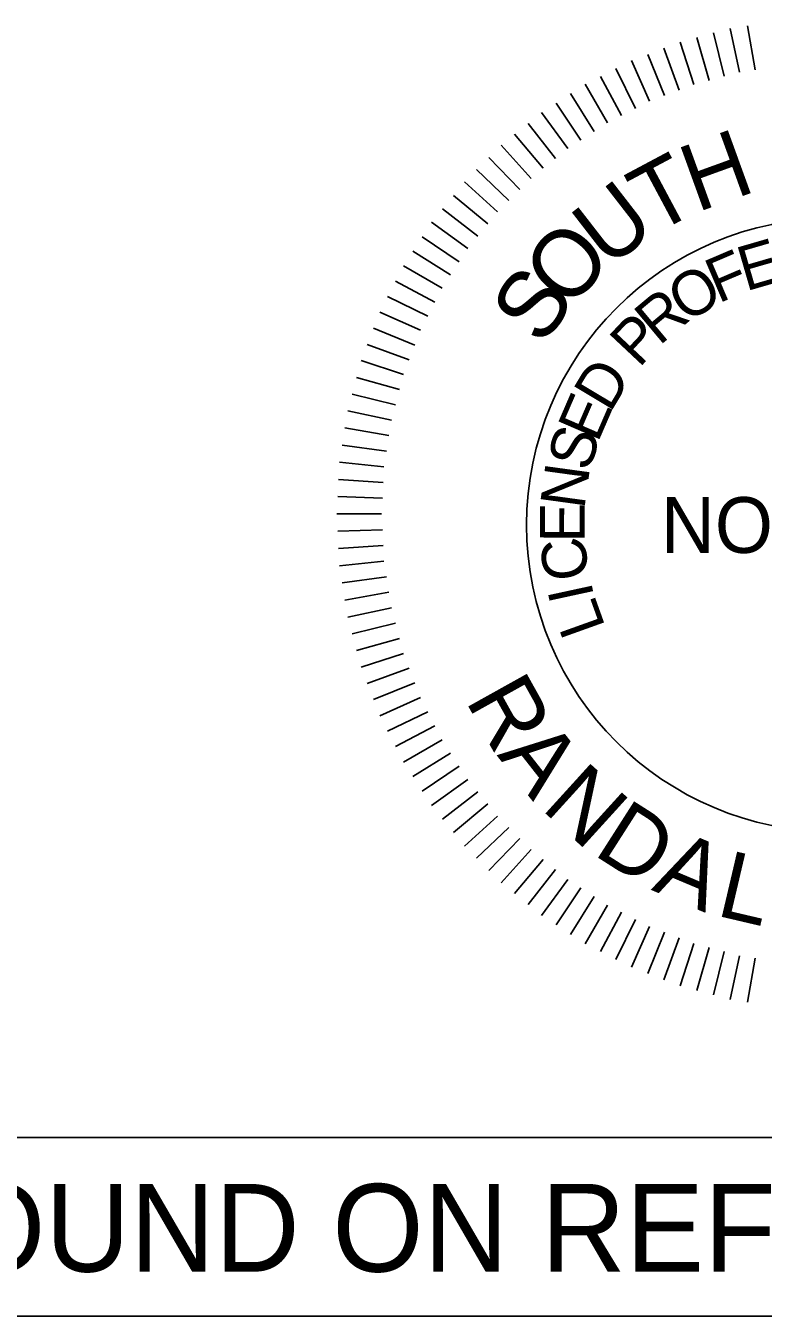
# Model space of a CAD drawing. Extents: x 1964849 to 1967422, y 1116563 to 1122211.
# Drawn here: x 1967263.8 to 1967322.6, y 1120529.2 to 1120632.2 of the extents above; entities that cross this region are included whole.
import ezdxf

# ---------------------------------------------------------------- set-up
doc = ezdxf.new("R2010")
doc.units = 0
doc.layers.add('RD_Sketch1', color=7, linetype='Continuous')
doc.layers.add('RD_TX_PEShield', color=7, linetype='Continuous')

msp = doc.modelspace()

# ---------------------------------------------------------------- linework, layer by layer
at = {"layer": 'RD_Sketch1'}
msp.add_lwpolyline([(1967105.7, 1120543.48), (1967406.12, 1120543.48), (1967406.12, 1120529.22), (1967105.7, 1120529.22)], close=True, dxfattribs=at)
at = {"layer": 'RD_TX_PEShield'}
for p, q in [((1967319.52, 1120628.17), (1967318.66, 1120631.62)), ((1967319.52, 1120628.17), (1967318.66, 1120631.62)), ((1967320.73, 1120628.5), (1967319.99, 1120631.98)), ((1967320.73, 1120628.5), (1967319.99, 1120631.98)), ((1967321.97, 1120628.69), (1967321.36, 1120632.19)), ((1967321.97, 1120628.69), (1967321.36, 1120632.19)), ((1967315.91, 1120627.07), (1967314.7, 1120630.41)), ((1967315.91, 1120627.07), (1967314.7, 1120630.41)), ((1967317.09, 1120627.52), (1967315.99, 1120630.9)), ((1967317.09, 1120627.52), (1967315.99, 1120630.9)), ((1967318.3, 1120627.84), (1967317.32, 1120631.26)), ((1967318.3, 1120627.84), (1967317.32, 1120631.26)), ((1967313.56, 1120626.17), (1967312.12, 1120629.42)), ((1967313.56, 1120626.17), (1967312.12, 1120629.42)), ((1967314.74, 1120626.62), (1967313.41, 1120629.91)), ((1967314.74, 1120626.62), (1967313.41, 1120629.91)), ((1967312.44, 1120625.6), (1967310.88, 1120628.79)), ((1967312.44, 1120625.6), (1967310.88, 1120628.79)), ((1967310.2, 1120624.45), (1967308.42, 1120627.54)), ((1967310.2, 1120624.45), (1967308.42, 1120627.54)), ((1967311.32, 1120625.03), (1967309.65, 1120628.16)), ((1967311.32, 1120625.03), (1967309.65, 1120628.16)), ((1967309.15, 1120623.77), (1967307.26, 1120626.78)), ((1967309.15, 1120623.77), (1967307.26, 1120626.78)), ((1967307.04, 1120622.4), (1967304.95, 1120625.28)), ((1967307.04, 1120622.4), (1967304.95, 1120625.28)), ((1967308.09, 1120623.08), (1967306.11, 1120626.03)), ((1967308.09, 1120623.08), (1967306.11, 1120626.03)), ((1967306.06, 1120621.61), (1967303.87, 1120624.41)), ((1967306.06, 1120621.61), (1967303.87, 1120624.41)), ((1967305.08, 1120620.82), (1967302.8, 1120623.54)), ((1967305.08, 1120620.82), (1967302.8, 1120623.54)), ((1967304.11, 1120620.02), (1967301.72, 1120622.67)), ((1967304.11, 1120620.02), (1967301.72, 1120622.67)), ((1967303.22, 1120619.14), (1967300.75, 1120621.69)), ((1967303.22, 1120619.14), (1967300.75, 1120621.69)), ((1967302.33, 1120618.25), (1967299.77, 1120620.72)), ((1967302.33, 1120618.25), (1967299.77, 1120620.72)), ((1967301.44, 1120617.36), (1967298.79, 1120619.74)), ((1967301.44, 1120617.36), (1967298.79, 1120619.74)), ((1967300.65, 1120616.38), (1967297.92, 1120618.66)), ((1967300.65, 1120616.38), (1967297.92, 1120618.66)), ((1967299.86, 1120615.4), (1967297.05, 1120617.59)), ((1967299.86, 1120615.4), (1967297.05, 1120617.59)), ((1967299.06, 1120614.42), (1967296.18, 1120616.52)), ((1967299.06, 1120614.42), (1967296.18, 1120616.52)), ((1967298.38, 1120613.37), (1967295.43, 1120615.36)), ((1967298.38, 1120613.37), (1967295.43, 1120615.36)), ((1967297.69, 1120612.32), (1967294.68, 1120614.2)), ((1967297.69, 1120612.32), (1967294.68, 1120614.2)), ((1967297.01, 1120611.26), (1967293.93, 1120613.04)), ((1967297.01, 1120611.26), (1967293.93, 1120613.04)), ((1967296.44, 1120610.14), (1967293.3, 1120611.81)), ((1967296.44, 1120610.14), (1967293.3, 1120611.81)), ((1967295.87, 1120609.02), (1967292.67, 1120610.58)), ((1967295.87, 1120609.02), (1967292.67, 1120610.58)), ((1967295.3, 1120607.9), (1967292.04, 1120609.35)), ((1967295.3, 1120607.9), (1967292.04, 1120609.35)), ((1967294.85, 1120606.72), (1967291.55, 1120608.06)), ((1967294.85, 1120606.72), (1967291.55, 1120608.06)), ((1967294.4, 1120605.55), (1967291.05, 1120606.77)), ((1967294.4, 1120605.55), (1967291.05, 1120606.77)), ((1967293.94, 1120604.38), (1967290.56, 1120605.48)), ((1967293.94, 1120604.38), (1967290.56, 1120605.48)), ((1967293.62, 1120603.16), (1967290.2, 1120604.14)), ((1967293.62, 1120603.16), (1967290.2, 1120604.14)), ((1967293.29, 1120601.95), (1967289.84, 1120602.81)), ((1967293.29, 1120601.95), (1967289.84, 1120602.81)), ((1967292.97, 1120600.73), (1967289.49, 1120601.47)), ((1967292.97, 1120600.73), (1967289.49, 1120601.47)), ((1967292.77, 1120599.49), (1967289.27, 1120600.11)), ((1967292.77, 1120599.49), (1967289.27, 1120600.11)), ((1967292.57, 1120598.25), (1967289.05, 1120598.74)), ((1967292.57, 1120598.25), (1967289.05, 1120598.74)), ((1967292.38, 1120597.01), (1967288.84, 1120597.38)), ((1967292.38, 1120597.01), (1967288.84, 1120597.38)), ((1967292.31, 1120595.75), (1967288.76, 1120596)), ((1967292.31, 1120595.75), (1967288.76, 1120596)), ((1967292.25, 1120594.49), (1967288.69, 1120594.62)), ((1967292.25, 1120594.49), (1967288.69, 1120594.62)), ((1967292.18, 1120593.24), (1967288.62, 1120593.24)), ((1967292.18, 1120593.24), (1967288.62, 1120593.24)), ((1967292.25, 1120591.98), (1967288.69, 1120591.86)), ((1967292.25, 1120591.98), (1967288.69, 1120591.86)), ((1967292.31, 1120590.73), (1967288.76, 1120590.48)), ((1967292.31, 1120590.73), (1967288.76, 1120590.48)), ((1967292.38, 1120589.47), (1967288.84, 1120589.1)), ((1967292.38, 1120589.47), (1967288.84, 1120589.1)), ((1967292.57, 1120588.23), (1967289.05, 1120587.73)), ((1967292.57, 1120588.23), (1967289.05, 1120587.73)), ((1967292.77, 1120586.99), (1967289.27, 1120586.37)), ((1967292.77, 1120586.99), (1967289.27, 1120586.37)), ((1967292.97, 1120585.74), (1967289.49, 1120585)), ((1967292.97, 1120585.74), (1967289.49, 1120585)), ((1967293.29, 1120584.53), (1967289.84, 1120583.67)), ((1967293.29, 1120584.53), (1967289.84, 1120583.67)), ((1967293.62, 1120583.31), (1967290.2, 1120582.33)), ((1967293.62, 1120583.31), (1967290.2, 1120582.33)), ((1967293.94, 1120582.1), (1967290.56, 1120581)), ((1967294.4, 1120580.92), (1967291.05, 1120579.71)), ((1967294.4, 1120580.92), (1967291.05, 1120579.71)), ((1967294.85, 1120579.75), (1967291.55, 1120578.42)), ((1967294.85, 1120579.75), (1967291.55, 1120578.42)), ((1967295.3, 1120578.58), (1967292.04, 1120577.13)), ((1967295.3, 1120578.58), (1967292.04, 1120577.13)), ((1967295.87, 1120577.46), (1967292.67, 1120575.9)), ((1967295.87, 1120577.46), (1967292.67, 1120575.9)), ((1967296.44, 1120576.34), (1967293.3, 1120574.67)), ((1967296.44, 1120576.34), (1967293.3, 1120574.67)), ((1967297.01, 1120575.22), (1967293.93, 1120573.44)), ((1967297.01, 1120575.22), (1967293.93, 1120573.44)), ((1967297.69, 1120574.16), (1967294.68, 1120572.28)), ((1967297.69, 1120574.16), (1967294.68, 1120572.28)), ((1967298.38, 1120573.11), (1967295.43, 1120571.12)), ((1967298.38, 1120573.11), (1967295.43, 1120571.12)), ((1967299.06, 1120572.05), (1967296.18, 1120569.96)), ((1967299.06, 1120572.05), (1967296.18, 1120569.96)), ((1967299.86, 1120571.07), (1967297.05, 1120568.88)), ((1967299.86, 1120571.07), (1967297.05, 1120568.88)), ((1967300.65, 1120570.1), (1967297.92, 1120567.81)), ((1967300.65, 1120570.1), (1967297.92, 1120567.81)), ((1967301.44, 1120569.12), (1967298.79, 1120566.74)), ((1967301.44, 1120569.12), (1967298.79, 1120566.74)), ((1967302.33, 1120568.23), (1967299.77, 1120565.76)), ((1967302.33, 1120568.23), (1967299.77, 1120565.76)), ((1967303.22, 1120567.34), (1967300.75, 1120564.78)), ((1967303.22, 1120567.34), (1967300.75, 1120564.78)), ((1967304.11, 1120566.45), (1967301.72, 1120563.81)), ((1967304.11, 1120566.45), (1967301.72, 1120563.81)), ((1967305.08, 1120565.66), (1967302.8, 1120562.94)), ((1967305.08, 1120565.66), (1967302.8, 1120562.94)), ((1967306.06, 1120564.87), (1967303.87, 1120562.07)), ((1967306.06, 1120564.87), (1967303.87, 1120562.07)), ((1967307.04, 1120564.08), (1967304.95, 1120561.2)), ((1967307.04, 1120564.08), (1967304.95, 1120561.2)), ((1967308.09, 1120563.39), (1967306.11, 1120560.44)), ((1967308.09, 1120563.39), (1967306.11, 1120560.44)), ((1967309.15, 1120562.71), (1967307.26, 1120559.69)), ((1967309.15, 1120562.71), (1967307.26, 1120559.69)), ((1967310.2, 1120562.02), (1967308.42, 1120558.94)), ((1967310.2, 1120562.02), (1967308.42, 1120558.94)), ((1967311.32, 1120561.45), (1967309.65, 1120558.31)), ((1967311.32, 1120561.45), (1967309.65, 1120558.31)), ((1967312.44, 1120560.88), (1967310.88, 1120557.68)), ((1967312.44, 1120560.88), (1967310.88, 1120557.68)), ((1967313.56, 1120560.31), (1967312.12, 1120557.06)), ((1967313.56, 1120560.31), (1967312.12, 1120557.06)), ((1967314.74, 1120559.86), (1967313.41, 1120556.56)), ((1967314.74, 1120559.86), (1967313.41, 1120556.56)), ((1967315.91, 1120559.41), (1967314.7, 1120556.07)), ((1967315.91, 1120559.41), (1967314.7, 1120556.07)), ((1967317.09, 1120558.96), (1967315.99, 1120555.57)), ((1967317.09, 1120558.96), (1967315.99, 1120555.57)), ((1967318.3, 1120558.63), (1967317.32, 1120555.21)), ((1967318.3, 1120558.63), (1967317.32, 1120555.21)), ((1967319.52, 1120558.31), (1967318.66, 1120554.86)), ((1967319.52, 1120558.31), (1967318.66, 1120554.86)), ((1967320.73, 1120557.98), (1967319.99, 1120554.5)), ((1967320.73, 1120557.98), (1967319.99, 1120554.5)), ((1967321.97, 1120557.78), (1967321.36, 1120554.28)), ((1967321.97, 1120557.78), (1967321.36, 1120554.28))]:
    msp.add_line(p, q, dxfattribs=at)
msp.add_circle((1967328.23, 1120592.36), 24.48, dxfattribs=at)

# ---------------------------------------------------------------- texts
at = {"layer": 'RD_Sketch1'}
msp.add_text('ALIGNMENT CONTROL CAN BE FOUND ON REFERENCE SHEET', height=7, dxfattribs=at).set_placement((1967109.35, 1120532.77))
at = {"layer": 'RD_TX_PEShield'}
for s, height, rotation, p in [('H', 5.34, 19.9102, (1967317.32, 1120617.28)), ('T', 5.34, 28.0947, (1967313.88, 1120615.48)), ('U', 5.34, 37.7726, (1967310.2, 1120612.74)), ('O', 5.34, 47.4504, (1967307.03, 1120609.42)), ('E', 3.56, 16.1843, (1967321.22, 1120610.99)), ('F', 3.56, 23.0853, (1967319.04, 1120610.02)), ('O', 3.56, 31.7869, (1967316.47, 1120608.42)), ('S', 5.34, 54.9027, (1967305, 1120606.52)), ('R', 3.56, 39.8902, (1967314.32, 1120606.61)), ('P', 3.56, 46.7912, (1967312.71, 1120604.83)), ('D', 3.56, 59.074, (1967310.41, 1120601.25)), ('E', 3.56, 66.5674, (1967309.41, 1120598.85)), ('S', 3.56, 73.4683, (1967308.76, 1120596.54)), ('N', 3.56, 82.17, (1967308.35, 1120593.55)), ('E', 3.56, 89.6633, (1967308.37, 1120590.95)), ('C', 3.56, 97.7667, (1967308.77, 1120588.16)), ('I', 3.56, 102.2511, (1967309.15, 1120586.65)), ('L', 3.56, 109.7445, (1967310.06, 1120584.21)), ('R', 5.34, 299.1493, (1967298.82, 1120578.39)), ('A', 5.34, 308.0877, (1967301.35, 1120573.99)), ('N', 5.34, 317.7655, (1967304.82, 1120569.73)), ('D', 5.34, 327.4433, (1967308.96, 1120566.12)), ('A', 5.34, 337.1212, (1967313.64, 1120563.25)), ('L', 5.34, 346.799, (1967318.75, 1120561.22))]:
    msp.add_text(s, height=height, rotation=rotation, dxfattribs=at).set_placement(p)
msp.add_text('NO. 24265', height=4.45, dxfattribs=at).set_placement((1967314.47, 1120590.13))

doc.saveas('drawing.dxf')
